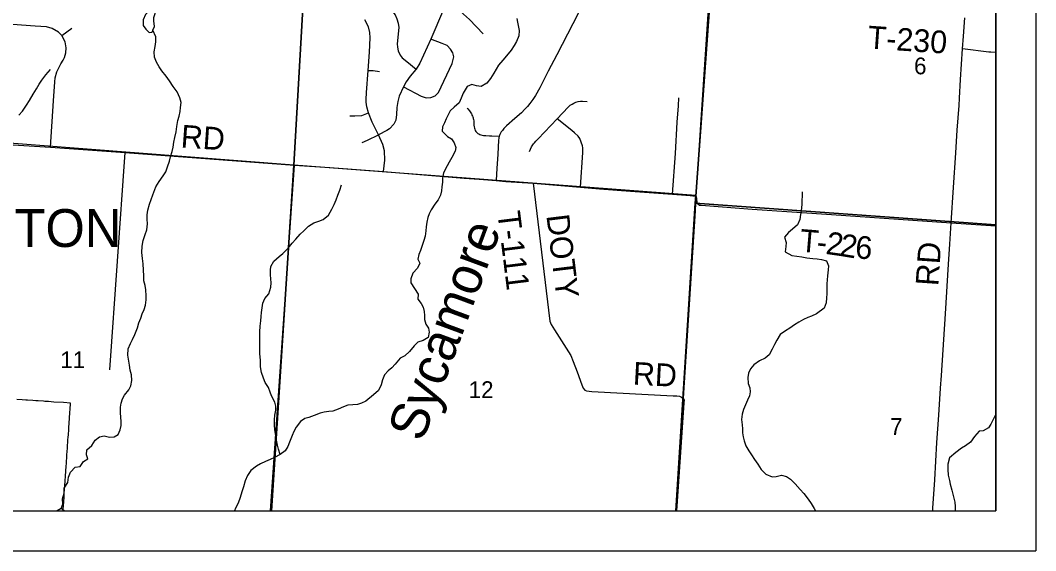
# Model space of a CAD drawing. Extents: x 0 to 34, y 0 to 22.
# Drawn here: x 6.46 to 9, y 14 to 15.327 of the extents above; entities that cross this region are included whole.
import ezdxf

# ---------------------------------------------------------------- set-up
doc = ezdxf.new("R2010")
doc.units = 0
for name, color, linetype in [('GM_X_Corporation', 7, 'Continuous'), ('GM_X_Corporation_Text', 7, 'Continuous'), ('GM_X_County_Road', 7, 'Continuous'), ('GM_X_County_Road_Text', 7, 'Continuous'), ('GM_X_Minor_Lake', 7, 'Continuous'), ('GM_X_Minor_River', 7, 'Continuous'), ('GM_X_Minor_River_Text', 7, 'Continuous'), ('GM_X_Section_Text', 7, 'Continuous'), ('GM_X_Township_Road', 7, 'Continuous'), ('GM_X_Township_Road_Text', 7, 'Continuous'), ('SH_Data', 7, 'Continuous')]:
    doc.layers.add(name, color=color, linetype=linetype)

msp = doc.modelspace()

# ---------------------------------------------------------------- linework, layer by layer
at = {"layer": 'GM_X_Corporation'}
for points in [[(3.0167, 14.1), (8.9, 14.1), (8.9, 17.9001), (8.3494, 17.9349), (8.1742, 17.9461), (7.8447, 17.9665), (7.5344, 17.9901), (7.2487, 18.0119), (6.5673, 18.064), (6.0904, 18.0983)], [(3.0167, 14.1), (8.1011, 14.1), (8.1079, 14.1976), (8.1194, 14.3701), (8.12, 14.3767), (8.1177, 14.3813), (8.1477, 14.8503), (8.1489, 14.8684), (8.1501, 14.8865), (8.1855, 15.3822), (8.215, 15.8988), (8.2214, 15.9952), (8.3153, 17.4178), (8.3494, 17.9349), (8.1742, 17.9461), (7.8447, 17.9665), (7.5344, 17.9901), (7.2487, 18.0119), (6.5673, 18.064), (6.0904, 18.0983)], [(3.0169, 14.1), (8.9, 14.1), (8.9, 17.8995), (8.3496, 17.9344), (8.1744, 17.9455), (7.8449, 17.9659), (7.5346, 17.9896), (7.2489, 18.0114), (6.5646, 18.0583), (6.0906, 18.0978)], [(6.3894, 14.1), (6.567, 14.1), (6.5681, 14.117), (6.5683, 14.1196), (6.5685, 14.1232), (6.5693, 14.1342), (6.5693, 14.1347), (6.5699, 14.1427), (6.5699, 14.1436), (6.5712, 14.1623), (6.5737, 14.1989), (6.5741, 14.2047), (6.5743, 14.2068), (6.5745, 14.2108), (6.5751, 14.2192), (6.5754, 14.2241), (6.576, 14.2323), (6.5763, 14.2373), (6.5772, 14.2505), (6.5775, 14.2542), (6.5781, 14.2637), (6.5786, 14.2703), (6.5791, 14.277), (6.5795, 14.2841), (6.58, 14.2902), (6.5809, 14.3034), (6.5814, 14.3107), (6.5818, 14.3166), (6.582, 14.3193), (6.5828, 14.3313), (6.5838, 14.346), (6.5844, 14.3544), (6.5853, 14.3685), (6.5854, 14.3692), (6.568, 14.3703), (6.5678, 14.3704), (6.544, 14.3719), (6.544, 14.3719), (6.5307, 14.3728), (6.5215, 14.3735), (6.5175, 14.3737), (6.5043, 14.3746), (6.4988, 14.375), (6.4911, 14.3755), (6.4778, 14.3764), (6.474, 14.3766), (6.4646, 14.3773), (6.4514, 14.3781)]]:
    msp.add_lwpolyline(points, dxfattribs=at)
for points in [[(8.1011, 14.1), (8.9, 14.1), (8.9, 17.9001), (8.3494, 17.9349), (8.3153, 17.4178), (8.2214, 15.9952), (8.215, 15.8988), (8.1855, 15.3822), (8.1501, 14.8865), (8.1489, 14.8684), (8.1477, 14.8503), (8.1177, 14.3813), (8.12, 14.3767), (8.1194, 14.3701), (8.1079, 14.1976)], [(6.1806, 16.0412), (6.6929, 16.0021), (7.2018, 15.9686), (7.1441, 14.9641), (6.1096, 15.0446)], [(7.2018, 15.9686), (7.7055, 15.9334), (8.2166, 15.8976), (8.1497, 14.8881), (7.1441, 14.9641)], [(8.9, 14.8153), (8.9, 15.8531), (8.7597, 15.8616), (8.2166, 15.8976), (8.1497, 14.8881), (8.1482, 14.8695)], [(6.0432, 14.1), (7.0881, 14.1), (7.1441, 14.9641), (6.1096, 15.0446)], [(7.0881, 14.1), (8.0996, 14.1), (8.1482, 14.8695), (8.1497, 14.8881), (7.1441, 14.9641)], [(8.0996, 14.1), (8.9, 14.1), (8.9, 14.8153), (8.1482, 14.8695)]]:
    msp.add_lwpolyline(points, close=True, dxfattribs=at)
at = {"layer": 'GM_X_County_Road'}
for points in [[(8.7889, 14.8204), (8.7946, 14.9088), (8.8002, 14.9956), (8.8039, 15.0517), (8.8082, 15.1136), (8.8093, 15.1322), (8.8119, 15.1788), (8.8169, 15.255), (8.819, 15.2872), (8.8226, 15.3327)], [(8.7427, 14.1), (8.743, 14.1061), (8.7475, 14.1774), (8.7529, 14.2704), (8.7575, 14.3386), (8.762, 14.4068), (8.7642, 14.4378), (8.7741, 14.5928), (8.7817, 14.7169), (8.7855, 14.7664), (8.7889, 14.8204)]]:
    msp.add_lwpolyline(points, dxfattribs=at)
at = {"layer": 'GM_X_Minor_Lake'}
for points in [[(6.7915, 15.3021), (6.7954, 15.3108), (6.794, 15.3252), (6.7937, 15.3339), (6.7965, 15.3411), (6.7989, 15.3506), (6.7993, 15.3548), (6.7932, 15.3556), (6.781, 15.3504), (6.773, 15.341), (6.7668, 15.3278), (6.7674, 15.3141), (6.7737, 15.3042), (6.7779, 15.3007), (6.7824, 15.2965)], [(6.7824, 15.2965), (6.7891, 15.2968), (6.7907, 15.2982), (6.7915, 15.3021)]]:
    msp.add_lwpolyline(points, dxfattribs=at)
at = {"layer": 'GM_X_Minor_River'}
for points in [[(7.7017, 15.3313), (7.7039, 15.3218), (7.7078, 15.3009), (7.7073, 15.2876), (7.7015, 15.274), (7.6957, 15.2638), (7.688, 15.2521), (7.6765, 15.2378), (7.6673, 15.2269), (7.6565, 15.2145), (7.65, 15.2043), (7.6446, 15.1945), (7.6357, 15.1813), (7.6273, 15.1693), (7.6124, 15.1611), (7.6014, 15.1631), (7.589, 15.1663), (7.5775, 15.1611), (7.5679, 15.1445), (7.5625, 15.132), (7.5574, 15.1203), (7.5448, 15.1094), (7.5352, 15.1004)], [(6.5619, 14.1056), (6.5658, 14.1162), (6.5656, 14.1295), (6.5696, 14.1435), (6.5693, 14.1564), (6.5786, 14.1707), (6.5806, 14.1836), (6.5853, 14.1964), (6.5972, 14.2088), (6.6093, 14.2102), (6.6181, 14.2227), (6.6284, 14.2301), (6.6255, 14.2397), (6.626, 14.2522), (6.639, 14.263), (6.6471, 14.2762), (6.6578, 14.2852), (6.6696, 14.287), (6.6828, 14.2842), (6.6949, 14.2849), (6.7045, 14.2905), (6.7099, 14.3022), (6.7119, 14.3131), (6.712, 14.3234), (6.711, 14.3344), (6.7104, 14.3447), (6.7105, 14.3587), (6.7121, 14.3689), (6.7157, 14.3795), (6.7207, 14.3893), (6.7314, 14.4025), (6.7361, 14.4127), (6.7385, 14.426), (6.7379, 14.4396), (6.735, 14.4514), (6.7332, 14.4643), (6.7307, 14.4788), (6.7286, 14.4894), (6.7295, 14.505), (6.7357, 14.5182), (6.7404, 14.528), (6.7466, 14.5409), (6.7528, 14.5571), (6.7567, 14.57), (6.761, 14.5813), (6.7649, 14.5923), (6.77, 14.6036), (6.7727, 14.6138), (6.7748, 14.6271), (6.7749, 14.6377), (6.7739, 14.6522), (6.7718, 14.6636), (6.7692, 14.6754), (6.7686, 14.6879), (6.7676, 14.7019), (6.767, 14.7175), (6.7657, 14.7312), (6.7639, 14.746), (6.7645, 14.7616), (6.7673, 14.7756), (6.7724, 14.7911), (6.7763, 14.8024), (6.7776, 14.8172), (6.7773, 14.829), (6.7774, 14.8404), (6.7787, 14.8517), (6.783, 14.8669), (6.7873, 14.8782), (6.7916, 14.8903), (6.7987, 14.91), (6.8071, 14.9239), (6.8175, 14.9379), (6.8237, 14.9477), (6.828, 14.9601), (6.8327, 14.9745), (6.8358, 14.9851), (6.8401, 14.9987), (6.8425, 15.0093), (6.8442, 15.0222), (6.8466, 15.0332), (6.8498, 15.0476), (6.8518, 15.0612), (6.8539, 15.0764), (6.857, 15.087), (6.8594, 15.0987), (6.8603, 15.109), (6.8623, 15.1211), (6.859, 15.1329), (6.852, 15.1478), (6.8426, 15.1611), (6.833, 15.1757), (6.8244, 15.1871), (6.8139, 15.2005), (6.8072, 15.2101), (6.8009, 15.2219), (6.7953, 15.2345), (6.7951, 15.2478), (6.7975, 15.2614), (6.7992, 15.2732), (6.7985, 15.2857), (6.7915, 15.3021)], [(6.4562, 15.0896), (6.4654, 15.0994), (6.4751, 15.1141), (6.4828, 15.1262), (6.4917, 15.142), (6.5001, 15.1552), (6.5067, 15.1669), (6.5136, 15.1771), (6.5236, 15.1906), (6.5351, 15.2034)], [(7.5352, 15.1004), (7.5298, 15.0906), (7.5251, 15.08), (7.5209, 15.0702), (7.5162, 15.0604), (7.5153, 15.049), (7.5288, 15.0363), (7.5386, 15.0305), (7.5453, 15.0206), (7.549, 15.0088), (7.5474, 14.999), (7.5393, 14.9835), (7.5323, 14.9722), (7.528, 14.9623), (7.5184, 14.945), (7.5164, 14.9321), (7.5159, 14.9219), (7.5146, 14.9105), (7.5134, 14.8999), (7.511, 14.8893), (7.5048, 14.8776), (7.4967, 14.867), (7.4875, 14.8527), (7.4828, 14.8429), (7.4793, 14.8331), (7.4769, 14.8217), (7.4749, 14.81), (7.474, 14.7997), (7.4724, 14.7868), (7.4692, 14.7759), (7.4641, 14.7607), (7.4606, 14.7509), (7.4567, 14.7411), (7.4543, 14.729), (7.4595, 14.7194), (7.4537, 14.7069), (7.4414, 14.6945), (7.4367, 14.6802), (7.4366, 14.6699), (7.446, 14.6558), (7.4553, 14.642), (7.454, 14.6295), (7.4626, 14.6184), (7.4678, 14.6089), (7.4703, 14.5986), (7.471, 14.588), (7.4713, 14.5785), (7.4745, 14.5663), (7.4809, 14.5568), (7.483, 14.5469), (7.4799, 14.5329), (7.4677, 14.5254), (7.4547, 14.5217), (7.4452, 14.5127), (7.4333, 14.4984), (7.4218, 14.4875), (7.41, 14.4812), (7.3973, 14.4669), (7.3893, 14.4571), (7.3797, 14.4496), (7.3709, 14.4395), (7.3655, 14.4274), (7.3627, 14.4149), (7.3561, 14.4009), (7.3438, 14.3897), (7.324, 14.3739), (7.3133, 14.3691), (7.303, 14.3658), (7.2917, 14.3648), (7.2792, 14.3638), (7.2685, 14.3601), (7.2552, 14.3538), (7.2419, 14.349), (7.2316, 14.3483), (7.2203, 14.3466), (7.2096, 14.3436), (7.1952, 14.3385), (7.1815, 14.3329), (7.172, 14.3304), (7.1605, 14.3233), (7.1502, 14.3093), (7.1444, 14.2984), (7.1401, 14.2882), (7.1335, 14.2716), (7.1288, 14.2606), (7.1222, 14.2497), (7.11, 14.2403), (7.0955, 14.2332), (7.0849, 14.228), (7.0731, 14.2232), (7.0609, 14.2173), (7.051, 14.2113), (7.0369, 14.2005), (7.028, 14.188), (7.0222, 14.1748), (7.0179, 14.16), (7.0143, 14.1476), (7.0096, 14.1332), (7.0045, 14.1192), (6.998, 14.106), (6.9956, 14.1)], [(7.11, 14.2403), (7.106, 14.2536), (7.1031, 14.2639), (7.1006, 14.2768), (7.0985, 14.2928), (7.0963, 14.3023), (7.0957, 14.3141), (7.0958, 14.327), (7.0963, 14.3387), (7.0987, 14.3512), (7.0992, 14.3611), (7.0967, 14.3718), (7.0885, 14.3874), (7.0852, 14.3969), (7.0804, 14.4084), (7.0726, 14.421), (7.0678, 14.4316), (7.0634, 14.4461), (7.0609, 14.4602), (7.0603, 14.4765), (7.0593, 14.4928), (7.0591, 14.5076), (7.0593, 14.5217), (7.059, 14.5327), (7.0592, 14.5475), (7.0601, 14.5619), (7.0614, 14.5752), (7.0626, 14.5862), (7.0635, 14.5956), (7.0651, 14.6074), (7.0664, 14.6191), (7.0718, 14.6308), (7.0818, 14.6421), (7.0865, 14.6592), (7.087, 14.6702), (7.0867, 14.68), (7.0861, 14.6903), (7.0858, 14.7013), (7.0867, 14.7108), (7.094, 14.7244), (7.107, 14.736), (7.1166, 14.7431), (7.1296, 14.7566), (7.1403, 14.7694), (7.1488, 14.7792), (7.1599, 14.792), (7.1695, 14.8002), (7.1809, 14.8115), (7.1939, 14.8197), (7.2068, 14.8245), (7.2175, 14.8282), (7.2305, 14.8394), (7.2394, 14.8542), (7.2452, 14.8662), (7.2498, 14.878), (7.2545, 14.8889), (7.2592, 14.9018), (7.2631, 14.9154)], [(8.4157, 14.8977), (8.4156, 14.8874), (8.4151, 14.8757), (8.4146, 14.8658), (8.4137, 14.8503), (8.412, 14.8408), (8.41, 14.8283), (8.4038, 14.8155), (8.3919, 14.8046), (8.382, 14.7963), (8.3713, 14.7839), (8.3761, 14.771), (8.3752, 14.7607), (8.3735, 14.7478), (8.3897, 14.7382), (8.4026, 14.7365), (8.4147, 14.7349), (8.4272, 14.7329), (8.4427, 14.7308), (8.4533, 14.7303), (8.4642, 14.7283), (8.4767, 14.7251), (8.4815, 14.7126), (8.4806, 14.7023), (8.4789, 14.6872), (8.4781, 14.6777), (8.4776, 14.6674), (8.4773, 14.6428), (8.4768, 14.6329), (8.4756, 14.6196), (8.4709, 14.6064), (8.4518, 14.5922), (8.4392, 14.5866), (8.4297, 14.5833), (8.4194, 14.5781), (8.4072, 14.5714), (8.3962, 14.5647), (8.3847, 14.5564), (8.374, 14.5497), (8.3607, 14.5404), (8.3522, 14.5268), (8.3468, 14.5159), (8.3406, 14.5038), (8.3333, 14.4902), (8.3229, 14.4819), (8.3088, 14.4753), (8.2951, 14.4648), (8.2867, 14.455), (8.2816, 14.444), (8.2796, 14.4334), (8.281, 14.4186), (8.2846, 14.4072), (8.2857, 14.3977), (8.284, 14.3875), (8.2794, 14.3769), (8.2739, 14.3648), (8.2693, 14.3531), (8.2657, 14.3417), (8.2637, 14.3285), (8.2654, 14.3148), (8.2665, 14.3049), (8.2667, 14.2947), (8.2685, 14.2844), (8.2707, 14.2749), (8.2751, 14.2619), (8.2822, 14.2497), (8.2889, 14.2398), (8.2967, 14.2279), (8.3049, 14.2161), (8.3135, 14.2035), (8.3251, 14.1912), (8.3406, 14.185), (8.3504, 14.1853), (8.3637, 14.1889), (8.3769, 14.1857), (8.3867, 14.1788), (8.398, 14.1669), (8.4111, 14.1527), (8.4197, 14.1432), (8.4309, 14.129), (8.438, 14.1179), (8.4454, 14.1057), (8.4493, 14.1)], [(8.9, 14.3418), (8.8999, 14.3416), (8.8945, 14.3295), (8.8875, 14.3167), (8.8817, 14.3069), (8.8688, 14.3002), (8.8589, 14.2987), (8.847, 14.286), (8.8366, 14.2716), (8.824, 14.2627), (8.8141, 14.2563), (8.8, 14.2455), (8.7847, 14.2323), (8.78, 14.2165), (8.7798, 14.2032), (8.7812, 14.1891), (8.7841, 14.1758), (8.7859, 14.1663), (8.7899, 14.1511), (8.7942, 14.1351), (8.7975, 14.121), (8.7985, 14.1108), (8.7988, 14.1)], [(6.5697, 14.1), (6.5619, 14.1056), (6.5518, 14.1)]]:
    msp.add_lwpolyline(points, dxfattribs=at)
at = {"layer": 'GM_X_Township_Road'}
for p, q in [((6.5637, 15.2886), (6.5889, 15.3067)), ((6.6837, 14.4525), (6.722, 14.9963)), ((7.086, 14.1), (7.1458, 14.9647)), ((8.7889, 14.8204), (8.9, 14.813))]:
    msp.add_line(p, q, dxfattribs=at)
for points in [[(7.3299, 15.4597), (7.3366, 15.4276), (7.3412, 15.4166), (7.3584, 15.3939), (7.3796, 15.3642), (7.3975, 15.3404), (7.4018, 15.3304), (7.4053, 15.3195), (7.4068, 15.3083), (7.403, 15.2678), (7.4032, 15.2593), (7.4053, 15.2507), (7.4099, 15.2397), (7.415, 15.2331), (7.4268, 15.2237), (7.45, 15.2045)], [(7.8839, 15.4007), (7.8417, 15.3177), (7.8018, 15.2405), (7.7806, 15.1991), (7.7591, 15.1579), (7.7484, 15.139), (7.7416, 15.1285), (7.7344, 15.1184), (7.7286, 15.1111), (7.7223, 15.1041), (7.7134, 15.0954), (7.6972, 15.081), (7.6762, 15.0626), (7.6696, 15.0561), (7.6657, 15.0514), (7.6627, 15.0475), (7.6608, 15.0443), (7.6591, 15.041), (7.6582, 15.0385), (7.6576, 15.0366), (7.6567, 15.0324), (7.656, 15.0264), (7.6552, 15.0104), (7.6541, 14.9909), (7.6519, 14.9568), (7.6499, 14.926)], [(7.5242, 15.3645), (7.5181, 15.3536), (7.4867, 15.2795), (7.4597, 15.2195), (7.45, 15.2045), (7.4493, 15.2037)], [(7.5247, 15.3654), (7.547, 15.3584), (7.5567, 15.3525), (7.5686, 15.3417), (7.5838, 15.3284), (7.6176, 15.2932)], [(6.5351, 15.0096), (6.5427, 15.1255), (6.5462, 15.1724), (6.5467, 15.1827), (6.5511, 15.1981), (6.561, 15.2179), (6.5674, 15.2274), (6.5702, 15.2334), (6.5736, 15.245), (6.5745, 15.258), (6.5719, 15.273), (6.5637, 15.2886), (6.5552, 15.2971), (6.5399, 15.3062), (6.5255, 15.3101), (6.4972, 15.3121), (6.3948, 15.3196), (6.3218, 15.325)], [(7.3686, 14.9483), (7.3714, 14.9768), (7.3711, 15.0004), (7.3671, 15.0161), (7.356, 15.0404), (7.3401, 15.0717), (7.3308, 15.0952), (7.3268, 15.1103), (7.3253, 15.1218), (7.3248, 15.1289), (7.3257, 15.1458), (7.3303, 15.2011), (7.3336, 15.2467), (7.3354, 15.2828), (7.3342, 15.2961), (7.3309, 15.3104), (7.322, 15.328)], [(7.4188, 15.1605), (7.463, 15.1371), (7.4753, 15.1331), (7.4866, 15.1333), (7.4973, 15.1379), (7.5063, 15.1458), (7.5398, 15.2183), (7.5446, 15.2357), (7.5415, 15.2452), (7.5362, 15.2543), (7.5277, 15.2633), (7.515, 15.2685), (7.4867, 15.2795)], [(8.9, 15.2458), (8.8876, 15.2468), (8.8825, 15.2473), (8.8169, 15.255)], [(7.3303, 15.2011), (7.3426, 15.2011), (7.3585, 15.1984)], [(7.4493, 15.2037), (7.4355, 15.1873), (7.4249, 15.1726), (7.4188, 15.1605), (7.4079, 15.1373), (7.4042, 15.1234), (7.4016, 15.1088), (7.4006, 15.0913), (7.399, 15.0769), (7.3942, 15.0665), (7.3833, 15.055), (7.3766, 15.051), (7.356, 15.0404)], [(7.8031, 15.0806), (7.8302, 15.1096), (7.8356, 15.1142), (7.84, 15.1172), (7.8445, 15.1197), (7.8497, 15.122), (7.8554, 15.1234), (7.8614, 15.1244), (7.8662, 15.1244), (7.8778, 15.1238)], [(8.0915, 14.8917), (8.0987, 14.9938), (8.1034, 15.0719), (8.1067, 15.1124), (8.1069, 15.133)], [(7.2838, 15.0881), (7.297, 15.0877), (7.3139, 15.0888), (7.3308, 15.0952)], [(7.5781, 15.1069), (7.5795, 15.1051), (7.5834, 15.1004), (7.5855, 15.0974), (7.5871, 15.095), (7.5885, 15.0925), (7.5891, 15.0911), (7.5897, 15.0898), (7.5909, 15.087), (7.5916, 15.0852), (7.5924, 15.0828), (7.5929, 15.081), (7.5935, 15.0782), (7.594, 15.0752), (7.5942, 15.0716), (7.5945, 15.068), (7.5947, 15.0635), (7.595, 15.0618), (7.5952, 15.0599), (7.5958, 15.0569), (7.5967, 15.054), (7.5981, 15.0513), (7.5998, 15.0487), (7.6017, 15.0463), (7.6027, 15.0453), (7.6042, 15.0439), (7.6066, 15.0425), (7.6093, 15.0412), (7.6122, 15.0402), (7.6152, 15.0394), (7.6182, 15.0389), (7.6243, 15.0382), (7.6338, 15.0378), (7.6396, 15.0375), (7.6576, 15.0366)], [(7.7338, 14.9988), (7.7387, 15.0099), (7.7403, 15.0129), (7.7434, 15.0174), (7.7461, 15.0206), (7.7493, 15.0241), (7.7556, 15.0306), (7.8031, 15.0806)], [(7.8616, 14.9093), (7.8668, 14.9964), (7.8671, 15.0077), (7.8663, 15.0125), (7.8633, 15.0222), (7.8595, 15.031), (7.855, 15.037), (7.8465, 15.045), (7.8395, 15.0508), (7.8031, 15.0806)], [(7.3147, 15.0213), (7.3285, 15.0269), (7.356, 15.0404)], [(6.2683, 15.0257), (6.5351, 15.0096), (6.722, 14.9963), (7.1458, 14.9647)], [(7.1458, 14.9647), (7.2344, 14.9586), (7.3686, 14.9483), (7.5704, 14.9317), (7.6074, 14.9295), (7.6499, 14.926)], [(7.6499, 14.926), (7.6748, 14.9235), (7.7427, 14.9192), (7.8616, 14.9093), (7.9086, 14.9053), (7.9866, 14.8992), (8.0915, 14.8917), (8.1356, 14.8885), (8.1481, 14.8871), (8.1503, 14.8859), (8.1518, 14.8806), (8.1524, 14.8702), (8.1592, 14.8645), (8.1621, 14.8645), (8.1631, 14.8644)], [(7.7427, 14.9192), (7.7849, 14.5739), (7.7881, 14.5656), (7.7958, 14.5527), (7.8371, 14.4884), (7.8433, 14.4735), (7.8527, 14.4475), (7.8643, 14.4148), (7.868, 14.4066), (7.8719, 14.4018), (7.8765, 14.3998), (7.89, 14.3986), (8.0928, 14.3876), (8.102, 14.3872), (8.1086, 14.3865), (8.1139, 14.3842), (8.1171, 14.3814)], [(8.1631, 14.8644), (8.2903, 14.8545), (8.4894, 14.841), (8.7889, 14.8204)], [(8.1171, 14.3814), (8.1179, 14.3807), (8.1203, 14.3762), (8.1197, 14.3695), (8.1082, 14.1971), (8.1013, 14.1)]]:
    msp.add_lwpolyline(points, dxfattribs=at)
at = {"layer": 'SH_Data'}
for p, q in [((9, 21), (9, 14)), ((8.9, 20.9), (8.9, 14.1)), ((2.1, 14.1), (8.9, 14.1)), ((2, 14), (9, 14))]:
    msp.add_line(p, q, dxfattribs=at)

# ---------------------------------------------------------------- texts
at = {"layer": 'GM_X_Corporation_Text'}
msp.add_text('PICKERINGTON', height=0.094697, rotation=0, dxfattribs=at).set_placement((5.7487, 14.7597))
at = {"layer": 'GM_X_County_Road_Text'}
msp.add_text('RD', height=0.05682, rotation=86.0545, dxfattribs=at).set_placement((8.7562, 14.661))
at = {"layer": 'GM_X_Minor_River_Text'}
msp.add_text('Sycamore', height=0.09469, rotation=69.6704, dxfattribs=at).set_placement((7.4657, 14.2692))
at = {"layer": 'GM_X_Section_Text'}
for s, height, p in [('6', 0.0419, (8.6957, 15.1916)), ('11', 0.04186, (6.5598, 14.4566)), ('12', 0.04186, (7.5815, 14.3819)), ('7', 0.0419, (8.6357, 14.2896))]:
    msp.add_text(s, height=height, rotation=0, dxfattribs=at).set_placement(p)
at = {"layer": 'GM_X_Township_Road_Text'}
for s, height, rotation, p in [('T-230', 0.05682, 356.0747, (8.5784, 15.2566)), ('RD', 0.05682, 356.055, (6.8601, 15.0088)), ('T-111', 0.05682, 277.0202, (7.6532, 14.8462)), ('DOTY', 0.05682, 276.971, (7.7758, 14.8384)), ('T', 0.0568, 355.315, (8.4082, 14.7482)), ('2', 0.0568, 351.9965, (8.4729, 14.7425)), ('2', 0.0568, 350.8174, (8.5073, 14.7377)), ('6', 0.0568, 355.9215, (8.5473, 14.7315)), ('-', 0.0568, 354.2218, (8.4503, 14.7448)), ('RD', 0.05682, 357.0388, (7.9914, 14.4155))]:
    msp.add_text(s, height=height, rotation=rotation, dxfattribs=at).set_placement(p)

doc.saveas('drawing.dxf')
